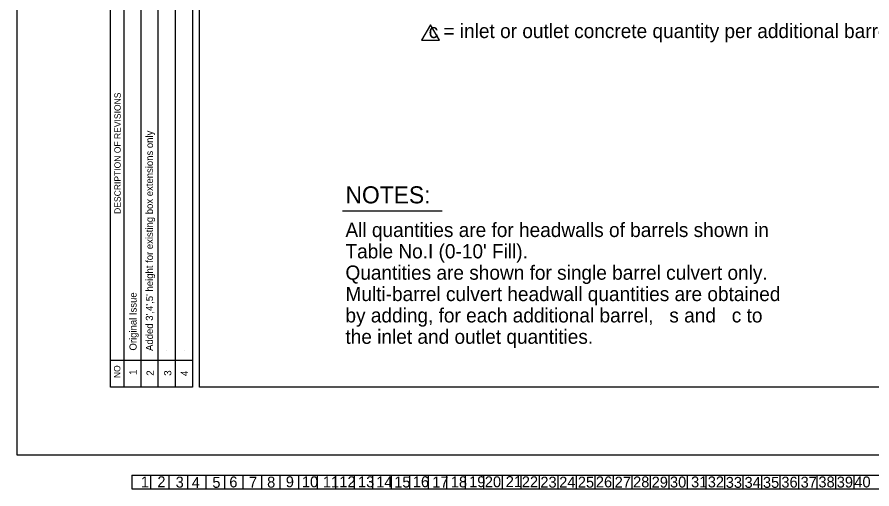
# Model space of a CAD drawing. Extents: x -0.08 to 2.83, y -0.03 to 1.92.
# Drawn here: x 0 to 0.782, y -0.031 to 0.401 of the extents above; entities that cross this region are included whole.
import ezdxf

# ---------------------------------------------------------------- set-up
doc = ezdxf.new("R2010")
doc.units = 0
for name, color, linetype in [('1', 7, 'Continuous'), ('10', 7, 'Continuous'), ('11', 7, 'Continuous'), ('12', 7, 'Continuous'), ('13', 7, 'Continuous'), ('14', 7, 'Continuous'), ('15', 7, 'Continuous'), ('16', 7, 'Continuous'), ('17', 7, 'Continuous'), ('18', 7, 'Continuous'), ('19', 7, 'Continuous'), ('2', 7, 'Continuous'), ('20', 7, 'Continuous'), ('21', 7, 'Continuous'), ('22', 7, 'Continuous'), ('23', 7, 'Continuous'), ('24', 7, 'Continuous'), ('25', 7, 'Continuous'), ('26', 7, 'Continuous'), ('27', 7, 'Continuous'), ('28', 7, 'Continuous'), ('29', 7, 'Continuous'), ('3', 7, 'Continuous'), ('30', 7, 'Continuous'), ('31', 7, 'Continuous'), ('32', 7, 'Continuous'), ('33', 7, 'Continuous'), ('34', 7, 'Continuous'), ('35', 7, 'Continuous'), ('36', 7, 'Continuous'), ('37', 7, 'Continuous'), ('38', 7, 'Continuous'), ('39', 7, 'Continuous'), ('4', 7, 'Continuous'), ('40', 7, 'Continuous'), ('5', 7, 'Continuous'), ('57', 7, 'Continuous'), ('6', 7, 'Continuous'), ('62', 7, 'Continuous'), ('63', 7, 'Continuous'), ('7', 7, 'Continuous'), ('8', 7, 'Continuous'), ('9', 7, 'Continuous')]:
    doc.layers.add(name, color=color, linetype=linetype)

msp = doc.modelspace()

# ---------------------------------------------------------------- linework, layer by layer
at = {"layer": '57'}
for p, q in [((0.37799, 0.39372), (0.36978, 0.37951)), ((0.38619, 0.37951), (0.37799, 0.39372)), ((0.36978, 0.37951), (0.38619, 0.37951)), ((0.29774, 0.22365), (0.38872, 0.22365))]:
    msp.add_line(p, q, dxfattribs=at)
at = {"layer": '62'}
for p, q in [((0.10603, 0.09579), (0.10603, 0.09579)), ((0.121, 0.09544), (0.121, 0.09544)), ((0.13668, 0.09544), (0.13668, 0.09544)), ((0.15304, 0.09579), (0.15304, 0.09579)), ((0.10494, -0.01804), (1.17174, -0.01804)), ((0.10494, -0.01804), (0.10494, -0.03074)), ((0.12188, -0.01804), (0.12188, -0.03074)), ((0.13881, -0.01804), (0.13881, -0.03074)), ((0.15574, -0.01804), (0.15574, -0.03074)), ((0.17267, -0.01804), (0.17267, -0.03074)), ((0.18961, -0.01804), (0.18961, -0.03074)), ((0.20654, -0.01804), (0.20654, -0.03074)), ((0.22348, -0.01804), (0.22348, -0.03074)), ((0.24041, -0.01804), (0.24041, -0.03074)), ((0.25734, -0.01804), (0.25734, -0.03074)), ((0.27427, -0.01804), (0.27427, -0.03074)), ((0.29121, -0.01804), (0.29121, -0.03074)), ((0.30814, -0.01804), (0.30814, -0.03074)), ((0.32508, -0.01804), (0.32508, -0.03074)), ((0.34201, -0.01804), (0.34201, -0.03074)), ((0.35894, -0.01804), (0.35894, -0.03074)), ((0.37588, -0.01804), (0.37588, -0.03074)), ((0.39281, -0.01804), (0.39281, -0.03074)), ((0.40974, -0.01804), (0.40974, -0.03074)), ((0.42668, -0.01804), (0.42668, -0.03074)), ((0.44361, -0.01804), (0.44361, -0.03074)), ((0.46054, -0.01804), (0.46054, -0.03074)), ((0.47748, -0.01804), (0.47748, -0.03074)), ((0.49441, -0.01804), (0.49441, -0.03074)), ((0.51134, -0.01804), (0.51134, -0.03074)), ((0.52828, -0.01804), (0.52828, -0.03074)), ((0.54521, -0.01804), (0.54521, -0.03074)), ((0.56214, -0.01804), (0.56214, -0.03074)), ((0.57908, -0.01804), (0.57908, -0.03074)), ((0.59601, -0.01804), (0.59601, -0.03074)), ((0.61294, -0.01804), (0.61294, -0.03074)), ((0.62988, -0.01804), (0.62988, -0.03074)), ((0.64681, -0.01804), (0.64681, -0.03074)), ((0.66374, -0.01804), (0.66374, -0.03074)), ((0.68068, -0.01804), (0.68068, -0.03074)), ((0.69761, -0.01804), (0.69761, -0.03074)), ((0.71454, -0.01804), (0.71454, -0.03074)), ((0.73147, -0.01804), (0.73147, -0.03074)), ((0.74841, -0.01804), (0.74841, -0.03074)), ((0.76534, -0.01804), (0.76534, -0.03074)), ((0.10494, -0.03074), (1.17174, -0.03074))]:
    msp.add_line(p, q, dxfattribs=at)
at = {"layer": '63'}
for p, q in [((0, 0), (0, 1.83333)), ((0.08543, 0.06244), (0.08543, 0.56244)), ((0.09792, 0.06244), (0.09792, 0.56244)), ((0.11353, 0.06259), (0.11353, 0.56244)), ((0.12914, 0.06275), (0.12914, 0.56244)), ((0.14474, 0.0629), (0.14474, 0.56244)), ((0.16043, 0.56244), (0.16043, 0.06244)), ((0.08543, 0.08707), (0.16043, 0.08707)), ((0.16043, 0.06244), (0.08543, 0.06244)), ((2.83333, 0), (0, 0))]:
    msp.add_line(p, q, dxfattribs=at)
msp.add_lwpolyline([(0.16668, 0.06244), (0.16668, 1.77077), (2.72918, 1.77077), (2.72918, 0.10411), (2.56251, 0.10411), (2.56251, 0.14578), (2.07387, 0.14578), (2.07387, 0.06244)], close=True, dxfattribs=at)

# ---------------------------------------------------------------- texts
at = {"layer": '1'}
msp.add_text('1', height=0.01, rotation=360, dxfattribs=at).set_placement((0.11316, -0.02944))
at = {"layer": '10'}
msp.add_text('10', height=0.01, rotation=360, dxfattribs=at).set_placement((0.26046, -0.02928))
at = {"layer": '11'}
msp.add_text('11', height=0.01, rotation=360, dxfattribs=at).set_placement((0.2796, -0.02937))
at = {"layer": '12'}
msp.add_text('12', height=0.01, rotation=360, dxfattribs=at).set_placement((0.29469, -0.02925))
at = {"layer": '13'}
msp.add_text('13', height=0.01, rotation=360, dxfattribs=at).set_placement((0.31181, -0.02928))
at = {"layer": '14'}
msp.add_text('14', height=0.01, rotation=360, dxfattribs=at).set_placement((0.32844, -0.02939))
at = {"layer": '15'}
msp.add_text('15', height=0.01, rotation=360, dxfattribs=at).set_placement((0.34488, -0.02946))
at = {"layer": '16'}
msp.add_text('16', height=0.01, rotation=360, dxfattribs=at).set_placement((0.3619, -0.02918))
at = {"layer": '17'}
msp.add_text('17', height=0.01, rotation=360, dxfattribs=at).set_placement((0.3797, -0.02946))
at = {"layer": '18'}
msp.add_text('18', height=0.01, rotation=360, dxfattribs=at).set_placement((0.39663, -0.02938))
at = {"layer": '19'}
msp.add_text('19', height=0.01, rotation=360, dxfattribs=at).set_placement((0.4134, -0.02918))
at = {"layer": '2'}
msp.add_text('2', height=0.01, rotation=360, dxfattribs=at).set_placement((0.12828, -0.02928))
at = {"layer": '20'}
msp.add_text('20', height=0.01, rotation=360, dxfattribs=at).set_placement((0.42774, -0.02926))
at = {"layer": '21'}
msp.add_text('21', height=0.01, rotation=360, dxfattribs=at).set_placement((0.44688, -0.02909))
at = {"layer": '22'}
msp.add_text('22', height=0.01, rotation=360, dxfattribs=at).set_placement((0.46158, -0.02929))
at = {"layer": '23'}
msp.add_text('23', height=0.01, rotation=360, dxfattribs=at).set_placement((0.47852, -0.02958))
at = {"layer": '24'}
msp.add_text('24', height=0.01, rotation=360, dxfattribs=at).set_placement((0.49576, -0.02958))
at = {"layer": '25'}
msp.add_text('25', height=0.01, rotation=360, dxfattribs=at).set_placement((0.51281, -0.02958))
at = {"layer": '26'}
msp.add_text('26', height=0.01, rotation=360, dxfattribs=at).set_placement((0.52931, -0.02936))
at = {"layer": '27'}
msp.add_text('27', height=0.01, rotation=360, dxfattribs=at).set_placement((0.54648, -0.02958))
at = {"layer": '28'}
msp.add_text('28', height=0.01, rotation=360, dxfattribs=at).set_placement((0.56333, -0.02938))
at = {"layer": '29'}
msp.add_text('29', height=0.01, rotation=360, dxfattribs=at).set_placement((0.58032, -0.02956))
at = {"layer": '3'}
msp.add_text('3', height=0.01, rotation=360, dxfattribs=at).set_placement((0.145, -0.02955))
at = {"layer": '30'}
msp.add_text('30', height=0.01, rotation=360, dxfattribs=at).set_placement((0.59706, -0.02946))
at = {"layer": '31'}
msp.add_text('31', height=0.01, rotation=360, dxfattribs=at).set_placement((0.61636, -0.02938))
at = {"layer": '32'}
msp.add_text('32', height=0.01, rotation=360, dxfattribs=at).set_placement((0.63163, -0.02938))
at = {"layer": '33'}
msp.add_text('33', height=0.01, rotation=360, dxfattribs=at).set_placement((0.64808, -0.02978))
at = {"layer": '34'}
msp.add_text('34', height=0.01, rotation=360, dxfattribs=at).set_placement((0.66527, -0.02978))
at = {"layer": '35'}
msp.add_text('35', height=0.01, rotation=360, dxfattribs=at).set_placement((0.68209, -0.02978))
at = {"layer": '36'}
msp.add_text('36', height=0.01, rotation=360, dxfattribs=at).set_placement((0.69895, -0.02958))
at = {"layer": '37'}
msp.add_text('37', height=0.01, rotation=360, dxfattribs=at).set_placement((0.71654, -0.02958))
at = {"layer": '38'}
msp.add_text('38', height=0.01, rotation=360, dxfattribs=at).set_placement((0.73281, -0.02938))
at = {"layer": '39'}
msp.add_text('39', height=0.01, rotation=360, dxfattribs=at).set_placement((0.74958, -0.0295))
at = {"layer": '4'}
msp.add_text('4', height=0.01, rotation=360, dxfattribs=at).set_placement((0.15973, -0.02984))
at = {"layer": '40'}
msp.add_text('40', height=0.01, rotation=360, dxfattribs=at).set_placement((0.76566, -0.02938))
at = {"layer": '5'}
msp.add_text('5', height=0.01, rotation=360, dxfattribs=at).set_placement((0.17858, -0.02977))
at = {"layer": '57'}
for s, height, p in [('  c = inlet or outlet concrete quantity per additional barrel.', 0.0130208, (0.36671, 0.38152)), ('NOTES:', 0.015625, (0.3003, 0.23035)), ('All quantities are for headwalls of barrels shown in', 0.0130208, (0.3003, 0.19959)), ("Table No.I (0-10' Fill).", 0.0130208, (0.3003, 0.18006)), ('Quantities are shown for single barrel culvert only.', 0.0130208, (0.3003, 0.16053)), ('Multi-barrel culvert headwall quantities are obtained', 0.0130208, (0.3003, 0.141)), ('by adding, for each additional barrel,   s and   c to', 0.0130208, (0.3003, 0.12147)), ('the inlet and outlet quantities.', 0.0130208, (0.3003, 0.10194))]:
    msp.add_text(s, height=height, dxfattribs=at).set_placement(p)
at = {"layer": '6'}
msp.add_text('6', height=0.01, rotation=360, dxfattribs=at).set_placement((0.19409, -0.02938))
at = {"layer": '62'}
for s, height, p in [("Added 3',4',5' height for existing box extensions only", 0.0065083, (0.12425, 0.09544)), ('Original Issue                                                   ', 0.0065084, (0.10928, 0.09579))]:
    msp.add_text(s, height=height, rotation=90, dxfattribs=at).set_placement(p)
at = {"layer": '63'}
for s, height, p in [('DESCRIPTION OF REVISIONS', 0.0058333, (0.09477, 0.22076)), ('NO', 0.005833, (0.09439, 0.07059)), ('1', 0.00667, (0.10936, 0.0735)), ('2', 0.00667, (0.12503, 0.07272)), ('3', 0.00667, (0.14105, 0.07272)), ('4', 0.00667, (0.15638, 0.07237))]:
    msp.add_text(s, height=height, rotation=90, dxfattribs=at).set_placement(p)
at = {"layer": '7'}
msp.add_text('7', height=0.01, rotation=360, dxfattribs=at).set_placement((0.21211, -0.02964))
at = {"layer": '8'}
msp.add_text('8', height=0.01, rotation=360, dxfattribs=at).set_placement((0.22865, -0.02958))
at = {"layer": '9'}
msp.add_text('9', height=0.01, rotation=360, dxfattribs=at).set_placement((0.24573, -0.02921))

doc.saveas('drawing.dxf')
